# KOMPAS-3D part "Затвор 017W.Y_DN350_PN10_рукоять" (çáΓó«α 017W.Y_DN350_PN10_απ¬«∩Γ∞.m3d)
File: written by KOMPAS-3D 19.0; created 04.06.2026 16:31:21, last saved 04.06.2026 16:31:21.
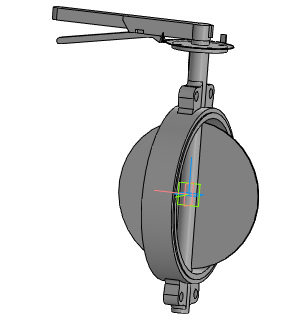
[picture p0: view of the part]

Document properties: Автор: Энергия; Полное имя файла: ..\..\..\3d для проектировщиков\017W разные\x.x Тип 017W.Y(S) Затвор дисковый поворотный межфланцевый\Затвор 017W.Y(S)_DN32-DN350_рукоять\Затвор 017W.Y_DN350_PN10_рукоять.a3d

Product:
- Part/product: Затвор 017W.Y_DN350_PN10_рукоять
    Масса: 31.1899

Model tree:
1. Операция без истории:1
